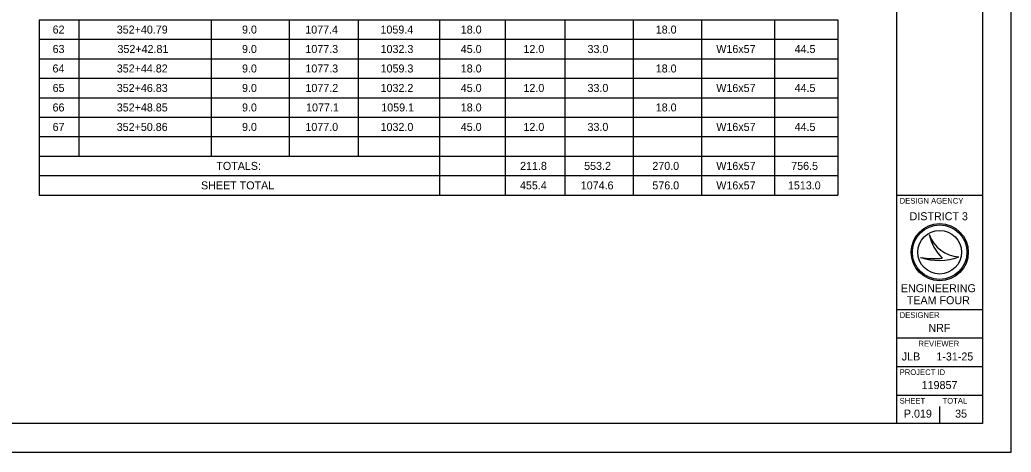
# Model space of a CAD drawing. Extents: x 0 to 34, y 0 to 22.
# Drawn here: x 16.67 to 34, y 0 to 7.57 of the extents above; entities that cross this region are included whole.
import ezdxf

# ---------------------------------------------------------------- set-up
doc = ezdxf.new("R2010")
doc.units = 0
for name, color, linetype in [('Default', 7, 'Continuous'), ('SH_Border', 7, 'Continuous'), ('SH_Cut_Line', 7, 'Continuous'), ('SH_Data', 7, 'Continuous')]:
    doc.layers.add(name, color=color, linetype=linetype)

msp = doc.modelspace()

# ---------------------------------------------------------------- linework, layer by layer
at = {"layer": 'Default'}
for p, q in [((17.006, 7.568), (20.013, 7.568)), ((17.006, 7.568), (17.006, 7.227)), ((17.7, 7.568), (17.7, 7.227)), ((20.013, 7.568), (30.969, 7.568)), ((20.013, 7.568), (20.013, 7.227)), ((21.376, 7.568), (21.376, 7.227)), ((22.581, 7.568), (22.581, 7.227)), ((24.006, 7.568), (24.006, 7.227)), ((25.15, 7.568), (25.15, 7.227)), ((26.197, 7.568), (26.197, 7.227)), ((27.39, 7.568), (27.39, 7.227)), ((28.583, 7.568), (28.583, 7.227)), ((29.861, 7.568), (29.861, 7.227)), ((30.969, 7.568), (30.969, 7.227)), ((17.006, 7.227), (20.013, 7.227)), ((17.006, 7.227), (17.006, 6.886)), ((17.7, 7.227), (17.7, 6.886)), ((20.013, 7.227), (30.969, 7.227)), ((20.013, 7.227), (20.013, 6.886)), ((21.376, 7.227), (21.376, 6.886)), ((22.581, 7.227), (22.581, 6.886)), ((24.006, 7.227), (24.006, 6.886)), ((25.15, 7.227), (25.15, 6.886)), ((26.197, 7.227), (26.197, 6.886)), ((27.39, 7.227), (27.39, 6.886)), ((28.583, 7.227), (28.583, 6.886)), ((29.861, 7.227), (29.861, 6.886)), ((30.969, 7.227), (30.969, 6.886)), ((17.006, 6.886), (20.013, 6.886)), ((17.006, 6.886), (17.006, 6.545)), ((17.7, 6.886), (17.7, 6.545)), ((20.013, 6.886), (30.969, 6.886)), ((20.013, 6.886), (20.013, 6.545)), ((21.376, 6.886), (21.376, 6.545)), ((22.581, 6.886), (22.581, 6.545)), ((24.006, 6.886), (24.006, 6.545)), ((25.15, 6.886), (25.15, 6.545)), ((26.197, 6.886), (26.197, 6.545)), ((27.39, 6.886), (27.39, 6.545)), ((28.583, 6.886), (28.583, 6.545)), ((29.861, 6.886), (29.861, 6.545)), ((30.969, 6.886), (30.969, 6.545)), ((17.006, 6.545), (20.013, 6.545)), ((17.006, 6.545), (17.006, 5.863)), ((17.7, 6.545), (17.7, 5.863)), ((20.013, 6.545), (30.969, 6.545)), ((20.013, 6.545), (20.013, 5.863)), ((21.376, 6.545), (21.376, 5.863)), ((22.581, 6.545), (22.581, 5.863)), ((24.006, 6.545), (24.006, 5.863)), ((25.15, 6.545), (25.15, 5.863)), ((26.197, 6.545), (26.197, 5.863)), ((27.39, 6.545), (27.39, 5.863)), ((28.583, 6.545), (28.583, 5.863)), ((29.861, 6.545), (29.861, 5.863)), ((30.969, 6.545), (30.969, 5.863)), ((17.006, 6.204), (20.013, 6.204)), ((20.013, 6.204), (30.969, 6.204)), ((17.006, 5.863), (20.013, 5.863)), ((17.006, 5.863), (17.006, 5.523)), ((17.7, 5.863), (17.7, 5.523)), ((20.013, 5.863), (30.969, 5.863)), ((20.013, 5.863), (20.013, 5.523)), ((21.376, 5.863), (21.376, 5.523)), ((22.581, 5.863), (22.581, 5.523)), ((24.006, 5.863), (24.006, 5.523)), ((25.15, 5.863), (25.15, 5.523)), ((26.197, 5.863), (26.197, 5.523)), ((27.39, 5.863), (27.39, 5.523)), ((28.583, 5.863), (28.583, 5.523)), ((29.861, 5.863), (29.861, 5.523)), ((30.969, 5.863), (30.969, 5.523)), ((17.006, 5.523), (20.013, 5.523)), ((17.006, 5.523), (17.006, 5.182)), ((17.7, 5.523), (17.7, 5.182)), ((20.013, 5.523), (30.969, 5.523)), ((20.013, 5.523), (20.013, 5.182)), ((21.376, 5.523), (21.376, 5.182)), ((22.581, 5.523), (22.581, 5.182)), ((24.006, 5.523), (24.006, 5.182)), ((25.15, 5.523), (25.15, 5.182)), ((26.197, 5.523), (26.197, 5.182)), ((27.39, 5.523), (27.39, 5.182)), ((28.583, 5.523), (28.583, 5.182)), ((29.861, 5.523), (29.861, 5.182)), ((30.969, 5.523), (30.969, 5.182)), ((17.006, 5.182), (20.013, 5.182)), ((17.006, 5.182), (17.006, 4.841)), ((20.013, 5.182), (30.969, 5.182)), ((24.006, 5.182), (24.006, 4.841)), ((25.15, 5.182), (25.15, 4.841)), ((26.197, 5.182), (26.197, 4.841)), ((27.39, 5.182), (27.39, 4.841)), ((28.583, 5.182), (28.583, 4.841)), ((29.861, 5.182), (29.861, 4.841)), ((30.969, 5.182), (30.969, 4.841)), ((17.006, 4.841), (20.013, 4.841)), ((17.006, 4.841), (17.006, 4.5)), ((20.013, 4.841), (30.969, 4.841)), ((24.006, 4.841), (24.006, 4.5)), ((25.15, 4.841), (25.15, 4.5)), ((26.197, 4.841), (26.197, 4.5)), ((27.39, 4.841), (27.39, 4.5)), ((28.583, 4.841), (28.583, 4.5)), ((29.861, 4.841), (29.861, 4.5)), ((30.969, 4.841), (30.969, 4.5)), ((17.006, 4.5), (20.013, 4.5)), ((20.013, 4.5), (30.969, 4.5))]:
    msp.add_line(p, q, dxfattribs=at)
at = {"layer": 'SH_Border'}
for p, q in [((32, 0.5), (32, 21.5)), ((32, 4.5), (33.5, 4.5)), ((32, 2.5), (33.5, 2.5)), ((32, 2), (33.5, 2)), ((32, 1.5), (33.5, 1.5)), ((32, 1), (33.5, 1))]:
    msp.add_line(p, q, dxfattribs=at)
msp.add_lwpolyline([(1.5, 21.5), (33.5, 21.5), (33.5, 0.5), (1.5, 0.5)], close=True, dxfattribs=at)
at = {"layer": 'SH_Cut_Line'}
msp.add_lwpolyline([(0, 0), (34, 0), (34, 22), (0, 22)], close=True, dxfattribs=at)
at = {"layer": 'SH_Data'}
for p, q in [((32.567, 3.81), (32.567, 3.81)), ((32.75, 3.5), (32.75, 3.5)), ((32.417, 3.41), (32.417, 3.41)), ((33.087, 3.419), (33.087, 3.419)), ((32.75, 0.5), (32.75, 0.8)), ((32.375, 0.675), (32.375, 0.675))]:
    msp.add_line(p, q, dxfattribs=at)
for radius in [0.5, 0.477, 0.477, 0.382]:
    msp.add_circle((32.75, 3.5), radius, dxfattribs=at)
for centre, radius, start, end in [((33.116, 3.998), 0.58, 198.9257, 198.9319), ((33.347, 3.97), 0.796, 191.6379, 191.6421), ((33.116, 3.998), 0.58, 198.9319, 267.1657), ((33.347, 3.97), 0.796, 191.6421, 226.0947), ((32.739, 4.37), 1.013, 251.4576, 290.0832), ((32.648, 4.654), 1.266, 259.4964, 259.4995), ((32.739, 4.37), 1.013, 251.4527, 251.4576), ((32.648, 4.654), 1.266, 259.4995, 276.6672)]:
    msp.add_arc(centre, radius, start, end, dxfattribs=at)

# ---------------------------------------------------------------- texts
at = {"layer": 'Default'}
for s, p in [('62', (17.239, 7.327)), ('352+40.79', (18.361, 7.327)), ('9.0', (20.551, 7.327)), ('1077.4', (21.657, 7.327)), ('1059.4', (22.972, 7.327)), ('18.0', (24.376, 7.327)), ('18.0', (27.785, 7.327)), ('63', (17.239, 6.987)), ('352+42.81', (18.373, 6.987)), ('9.0', (20.551, 6.987)), ('1077.3', (21.659, 6.987)), ('1032.3', (22.974, 6.987)), ('45.0', (24.376, 6.987)), ('12.0', (25.472, 6.987)), ('33.0', (26.592, 6.987)), ('W16x57', (28.844, 6.987)), ('44.5', (30.213, 6.987)), ('64', (17.237, 6.646)), ('352+44.82', (18.361, 6.646)), ('9.0', (20.551, 6.646)), ('1077.3', (21.659, 6.646)), ('1059.3', (22.974, 6.646)), ('18.0', (24.376, 6.646)), ('18.0', (27.785, 6.646)), ('65', (17.239, 6.305)), ('352+46.83', (18.361, 6.305)), ('9.0', (20.551, 6.305)), ('1077.2', (21.66, 6.305)), ('1032.2', (22.974, 6.305)), ('45.0', (24.376, 6.305)), ('12.0', (25.472, 6.305)), ('33.0', (26.592, 6.305)), ('W16x57', (28.844, 6.305)), ('44.5', (30.213, 6.305)), ('66', (17.238, 5.964)), ('352+48.85', (18.361, 5.964)), ('9.0', (20.551, 5.964)), ('1077.1', (21.671, 5.964)), ('1059.1', (22.986, 5.964)), ('18.0', (24.376, 5.964)), ('18.0', (27.785, 5.964)), ('67', (17.239, 5.623)), ('352+50.86', (18.36, 5.623)), ('9.0', (20.551, 5.623)), ('1077.0', (21.659, 5.623)), ('1032.0', (22.974, 5.623)), ('45.0', (24.376, 5.623)), ('12.0', (25.472, 5.623)), ('33.0', (26.592, 5.623)), ('W16x57', (28.844, 5.623)), ('44.5', (30.213, 5.623)), ('TOTALS:', (20.102, 4.941)), ('211.8', (25.413, 4.941)), ('553.2', (26.533, 4.941)), ('270.0', (27.726, 4.941)), ('W16x57', (28.844, 4.941)), ('756.5', (30.154, 4.941)), ('SHEET TOTAL', (19.834, 4.6)), ('455.4', (25.411, 4.6)), ('1074.6', (26.474, 4.6)), ('576.0', (27.726, 4.6)), ('W16x57', (28.844, 4.6)), ('1513.0', (30.096, 4.6))]:
    msp.add_text(s, height=0.14, dxfattribs=at).set_placement(p)
at = {"layer": 'SH_Data'}
for s, height, p in [('DESIGN AGENCY', 0.1, (32.05, 4.35)), ('DISTRICT 3', 0.14, (32.224, 4.06)), ('ENGINEERING', 0.14, (32.071, 2.8)), ('TEAM FOUR', 0.14, (32.175, 2.59)), ('DESIGNER', 0.1, (32.05, 2.35)), ('NRF', 0.14, (32.553, 2.105)), ('REVIEWER', 0.1, (32.378, 1.85)), ('JLB', 0.14, (32.087, 1.605)), ('1-31-25', 0.14, (32.692, 1.605)), ('PROJECT ID', 0.1, (32.05, 1.35)), ('119857', 0.14, (32.435, 1.105)), ('SHEET', 0.1, (32.05, 0.85)), ('TOTAL', 0.1, (32.8, 0.85)), ('P.019', 0.14, (32.124, 0.605)), ('35', 0.14, (33.02, 0.605))]:
    msp.add_text(s, height=height, dxfattribs=at).set_placement(p)

doc.saveas('drawing.dxf')
